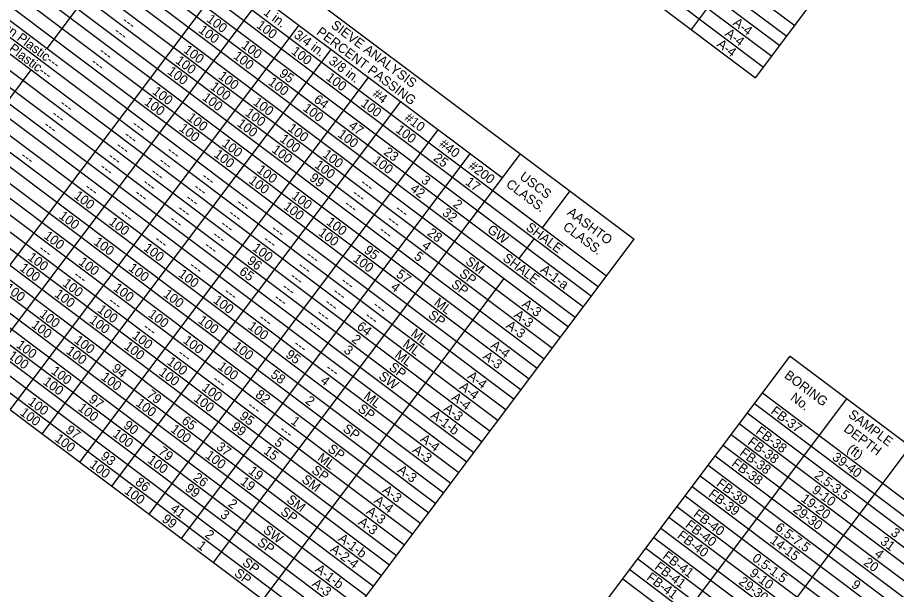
# Model space of a CAD drawing. Extents: x 627484.2 to 627517.5, y 367968.7 to 367996.9.
# Drawn here: x 627506.06 to 627511.18, y 367973.07 to 367976.4 of the extents above; entities that cross this region are included whole.
import ezdxf

# ---------------------------------------------------------------- set-up
doc = ezdxf.new("R2010")
doc.units = 0
doc.layers.add('Default', color=7, linetype='Continuous')
doc.layers.add('R_Survey Control', color=7, linetype='Continuous')

msp = doc.modelspace()

# ---------------------------------------------------------------- linework, layer by layer
at = {"layer": 'Default'}
for p, q in [((627506.113, 367979.7126), (627510.5882, 367976.3521)), ((627506.0661, 367979.6503), (627510.5414, 367976.2898)), ((627506.0251, 367979.5957), (627510.5004, 367976.2352)), ((627505.9783, 367979.5333), (627510.4536, 367976.1728)), ((627505.9315, 367979.4709), (627510.4067, 367976.1104)), ((627505.8846, 367979.4086), (627510.3599, 367976.0481)), ((627505.1779, 367978.4674), (627509.6531, 367975.1069)), ((627510.3599, 367976.0481), (627512.1221, 367978.3948)), ((627505.0169, 367978.253), (627509.4921, 367974.8925)), ((627504.97, 367978.1906), (627509.4453, 367974.8301)), ((627504.9291, 367978.136), (627509.4043, 367974.7755)), ((627504.8822, 367978.0736), (627509.3575, 367974.7131)), ((627504.8354, 367978.0113), (627509.3106, 367974.6508)), ((627504.7944, 367977.9567), (627509.2696, 367974.5962)), ((627504.7476, 367977.8943), (627509.2228, 367974.5338)), ((627504.7007, 367977.8319), (627509.176, 367974.4714)), ((627504.6539, 367977.7696), (627509.1291, 367974.4091)), ((627504.6129, 367977.715), (627509.0882, 367974.3545)), ((627504.5661, 367977.6526), (627509.0413, 367974.2921)), ((627504.5192, 367977.5902), (627508.9945, 367974.2297)), ((627504.4783, 367977.5357), (627508.9535, 367974.1752)), ((627504.4314, 367977.4733), (627508.9067, 367974.1128)), ((627504.3846, 367977.4109), (627508.8598, 367974.0504)), ((627504.3377, 367977.3486), (627508.813, 367973.9881)), ((627504.2909, 367977.2862), (627508.7662, 367973.9257)), ((627504.2441, 367977.2238), (627508.7193, 367973.8633)), ((627504.2031, 367977.1692), (627508.6783, 367973.8087)), ((627504.1563, 367977.1069), (627508.6315, 367973.7464)), ((627506.2325, 367976.2184), (627506.8765, 367977.076)), ((627504.1094, 367977.0445), (627508.5847, 367973.684)), ((627509.9856, 367976.3291), (627510.5301, 367977.0542)), ((627504.0684, 367976.9899), (627508.5437, 367973.6294)), ((627504.0216, 367976.9275), (627508.4968, 367973.567)), ((627503.9806, 367976.873), (627508.4559, 367973.5125)), ((627503.9338, 367976.8106), (627508.409, 367973.4501)), ((627505.6113, 367974.417), (627507.3999, 367976.7988)), ((627503.8869, 367976.7482), (627508.3622, 367973.3877)), ((627503.8401, 367976.6858), (627508.3154, 367973.3253)), ((627507.2945, 367976.6585), (627508.885, 367975.4642)), ((627503.7933, 367976.6235), (627508.2685, 367973.263)), ((627503.7523, 367976.5689), (627508.2275, 367973.2084)), ((627503.7055, 367976.5065), (627508.1807, 367973.146)), ((627505.7985, 367974.2765), (627507.4816, 367976.518)), ((627503.6586, 367976.4441), (627508.1339, 367973.0836)), ((627503.6176, 367976.3896), (627508.0929, 367973.0291)), ((627506.0168, 367974.1125), (627507.6999, 367976.354)), ((627503.5708, 367976.3272), (627508.046, 367972.9667)), ((627503.524, 367976.2648), (627507.9992, 367972.9043)), ((627503.483, 367976.2103), (627507.9582, 367972.8497)), ((627506.2039, 367973.972), (627507.8871, 367976.2135)), ((627503.4361, 367976.1479), (627507.9114, 367972.7874)), ((627503.3893, 367976.0855), (627507.8646, 367972.725)), ((627505.9573, 367975.852), (627506.1388, 367976.0937)), ((627506.4222, 367973.8081), (627508.1054, 367976.0496)), ((627506.6093, 367973.6676), (627508.2925, 367975.9091)), ((627506.8276, 367973.5037), (627508.5108, 367975.7452)), ((627507.0147, 367973.3631), (627508.6979, 367975.6047)), ((627507.2018, 367973.2226), (627508.9904, 367975.6045)), ((627508.8294, 367975.3901), (627509.4921, 367974.8925)), ((627509.1179, 367975.1735), (627509.2789, 367975.3879)), ((627508.9832, 367974.9942), (627509.071, 367975.1111)), ((627507.8646, 367972.725), (627509.6531, 367975.1069)), ((627507.4903, 367973.006), (627508.8954, 367974.8772)), ((627508.7721, 367972.0435), (627510.5607, 367974.4254)), ((627510.5607, 367974.4254), (627515.0359, 367971.0649)), ((627510.3997, 367974.211), (627514.8749, 367970.8505)), ((627509.1034, 367971.7947), (627510.892, 367974.1766)), ((627510.3528, 367974.1486), (627514.8281, 367970.7881)), ((627510.3118, 367974.094), (627514.7871, 367970.7335)), ((627510.265, 367974.0317), (627514.7402, 367970.6712)), ((627510.2182, 367973.9693), (627514.6934, 367970.6088)), ((627509.4738, 367971.5166), (627511.2623, 367973.8985)), ((627510.1713, 367973.9069), (627514.6466, 367970.5464)), ((627510.1245, 367973.8445), (627514.5997, 367970.484)), ((627510.0835, 367973.79), (627514.5588, 367970.4295)), ((627510.0367, 367973.7276), (627514.5119, 367970.3671)), ((627509.9898, 367973.6652), (627514.4651, 367970.3047)), ((627509.9489, 367973.6106), (627514.4241, 367970.2501)), ((627509.902, 367973.5483), (627514.3773, 367970.1878)), ((627509.8552, 367973.4859), (627514.3304, 367970.1254)), ((627509.8083, 367973.4235), (627514.2836, 367970.063)), ((627509.7674, 367973.3689), (627514.2426, 367970.0084)), ((627509.7205, 367973.3066), (627514.1958, 367969.9461)), ((627509.6737, 367973.2442), (627514.1489, 367969.8837)), ((627509.6269, 367973.1818), (627514.1021, 367969.8213)), ((627509.5859, 367973.1273), (627514.0611, 367969.7667))]:
    msp.add_line(p, q, dxfattribs=at)
at = {"layer": 'R_Survey Control'}
msp.add_line((627510.5607, 367974.4254), (627510.5607, 367974.4254), dxfattribs=at)

# ---------------------------------------------------------------- texts
at = {"layer": 'Default'}
for s, p in [('1 in.', (627507.4882, 367976.4207)), ('---Non Plastic---', (627505.8691, 367976.4081)), ('100', (627507.1571, 367976.3798)), ('A-4', (627510.2239, 367976.3596)), ('---Non Plastic---', (627505.8222, 367976.3457)), ('---', (627506.6646, 367976.3716)), ('100', (627507.1103, 367976.3174)), ('100', (627507.4477, 367976.3445)), ('PERCENT PASSING', (627507.797, 367976.3049)), ('SIEVE ANALYSIS', (627507.8818, 367976.3444)), ('---', (627506.6177, 367976.3093)), ('3/4 in.', (627507.6656, 367976.2875)), ('A-4', (627510.1771, 367976.2972)), ('100', (627507.3598, 367976.2275)), ('A-4', (627510.1303, 367976.2349)), ('---', (627506.5299, 367976.1923)), ('100', (627507.0225, 367976.2004)), ('100', (627507.313, 367976.1652)), ('100', (627507.6504, 367976.1923)), ('---', (627506.4831, 367976.1299)), ('100', (627506.9756, 367976.1381)), ('3/8 in.', (627507.8683, 367976.1353)), ('100', (627506.9288, 367976.0757)), ('95', (627507.5798, 367976.0624)), ('100', (627507.2252, 367976.0482)), ('100', (627507.5157, 367976.013)), ('100', (627507.8531, 367976.0401)), ('100', (627506.841, 367975.9587)), ('100', (627507.1783, 367975.9859)), ('100', (627507.1315, 367975.9235)), ('64', (627507.7815, 367975.9109)), ('#4', (627508.1234, 367975.9438)), ('---', (627506.3016, 367975.8883)), ('100', (627506.7941, 367975.8964)), ('100', (627507.4279, 367975.896)), ('100', (627507.7184, 367975.8607)), ('100', (627508.0558, 367975.8878)), ('---', (627506.2548, 367975.8259)), ('100', (627507.0437, 367975.8065)), ('100', (627507.3811, 367975.8336)), ('#10', (627508.3097, 367975.8039)), ('---', (627506.2079, 367975.7635)), ('---', (627506.7227, 367975.7671)), ('100', (627506.9969, 367975.7442)), ('100', (627507.3342, 367975.7713)), ('47', (627507.9845, 367975.7585)), ('100', (627507.6306, 367975.7438)), ('100', (627507.9211, 367975.7085)), ('100', (627508.2585, 367975.7356)), ('---', (627506.6759, 367975.7047)), ('100', (627507.2464, 367975.6543)), ('100', (627507.5838, 367975.6814)), ('#40', (627508.5124, 367975.6517)), ('---', (627506.6291, 367975.6424)), ('---', (627506.9254, 367975.6149)), ('100', (627507.1996, 367975.5919)), ('100', (627507.5369, 367975.619)), ('100', (627507.8333, 367975.5916)), ('23', (627508.1885, 367975.6053)), ('---', (627506.0733, 367975.5842)), ('---', (627506.5822, 367975.58)), ('100', (627508.1238, 367975.5563)), ('25', (627508.4784, 367975.5705)), ('---', (627506.5354, 367975.5176)), ('---', (627506.8786, 367975.5525)), ('100', (627507.4491, 367975.5021)), ('100', (627507.7865, 367975.5292)), ('#200', (627508.6832, 367975.5234)), ('---', (627506.8318, 367975.4901)), ('---', (627507.1282, 367975.4627)), ('100', (627507.4023, 367975.4397)), ('99', (627507.7561, 367975.4545)), ('3', (627508.4074, 367975.4409)), ('USCS', (627508.9806, 367975.4614)), ('---', (627506.4476, 367975.4007)), ('---', (627506.7849, 367975.4278)), ('---', (627508.0524, 367975.427)), ('42', (627508.343, 367975.3917)), ('17', (627508.6649, 367975.4305)), ('CLASS.', (627508.9013, 367975.4178)), ('100', (627506.3843, 367975.3506)), ('---', (627506.7381, 367975.3654)), ('---', (627507.0813, 367975.4003)), ('100', (627507.6518, 367975.3499)), ('---', (627508.0056, 367975.3647)), ('---', (627507.0345, 367975.3379)), ('---', (627507.3309, 367975.3105)), ('100', (627507.605, 367975.2875)), ('---', (627507.9588, 367975.3023)), ('2', (627508.5932, 367975.3014)), ('100', (627506.2965, 367975.2337)), ('---', (627506.6503, 367975.2485)), ('---', (627506.9876, 367975.2756)), ('---', (627507.284, 367975.2481)), ('---', (627508.2551, 367975.2748)), ('32', (627508.5301, 367975.2512)), ('AASHTO', (627509.2576, 367975.2534)), ('100', (627506.587, 367975.1984)), ('---', (627506.9408, 367975.2132)), ('100', (627507.8545, 367975.1977)), ('---', (627508.2083, 367975.2124)), ('---', (627507.2372, 367975.1857)), ('---', (627507.5336, 367975.1582)), ('100', (627507.8077, 367975.1353)), ('---', (627508.1615, 367975.1501)), ('28', (627508.4428, 367975.1339)), ('GW', (627508.792, 367975.1521)), ('SHALE', (627509.017, 367975.1661)), ('CLASS.', (627509.2327, 367975.169)), ('100', (627506.2087, 367975.1167)), ('100', (627506.4992, 367975.0814)), ('---', (627506.853, 367975.0962)), ('---', (627507.1904, 367975.1233)), ('---', (627507.4867, 367975.0959)), ('100', (627506.7898, 367975.0462)), ('---', (627507.1435, 367975.061)), ('100', (627507.4235, 367975.0458)), ('95', (627508.0745, 367975.0325)), ('4', (627508.4115, 367975.0599)), ('100', (627506.115, 367974.992)), ('---', (627506.1783, 367975.042)), ('---', (627507.7363, 367975.006)), ('100', (627508.0104, 367974.9831)), ('5', (627508.3657, 367974.9967)), ('SHALE', (627508.8823, 367974.9868)), ('100', (627506.0682, 367974.9296)), ('100', (627506.4114, 367974.9645)), ('100', (627506.7019, 367974.9292)), ('---', (627507.0557, 367974.944)), ('96', (627507.393, 367974.9712)), ('---', (627507.6895, 367974.9436)), ('SM', (627508.665, 367974.9671)), ('---', (627506.381, 367974.8898)), ('100', (627506.9925, 367974.894)), ('65', (627507.3471, 367974.9081)), ('57', (627508.2609, 367974.8925)), ('SP', (627508.6294, 367974.8962)), ('A-1-a', (627509.1016, 367974.9197)), ('100', (627506.3177, 367974.8398)), ('---', (627507.6426, 367974.8813)), ('---', (627507.939, 367974.8538)), ('SP', (627508.5826, 367974.8338)), ('100', (627505.9804, 367974.8126)), ('100', (627506.2709, 367974.7774)), ('100', (627506.6141, 367974.8123)), ('100', (627506.9046, 367974.777)), ('---', (627507.2584, 367974.7918)), ('---', (627507.5958, 367974.8189)), ('---', (627507.8922, 367974.7914)), ('4', (627508.23, 367974.8182)), ('---', (627506.5837, 367974.7376)), ('100', (627507.1952, 367974.7417)), ('---', (627507.5489, 367974.7565)), ('ML', (627508.4817, 367974.7267)), ('100', (627506.5204, 367974.6875)), ('---', (627507.8453, 367974.7291)), ('---', (627508.1261, 367974.7133)), ('A-3', (627508.9948, 367974.7194)), ('100', (627506.1831, 367974.6604)), ('100', (627506.4736, 367974.6252)), ('100', (627506.8168, 367974.6601)), ('100', (627507.1074, 367974.6248)), ('---', (627507.4611, 367974.6396)), ('---', (627507.7985, 367974.6667)), ('---', (627508.0793, 367974.6509)), ('SP', (627508.4479, 367974.6545)), ('A-3', (627508.9479, 367974.657)), ('100', (627506.1362, 367974.5981)), ('---', (627506.7864, 367974.5854)), ('100', (627507.3979, 367974.5895)), ('---', (627507.7517, 367974.6043)), ('64', (627508.0323, 367974.5887)), ('A-3', (627508.9011, 367974.5947)), ('100', (627506.7232, 367974.5353)), ('2', (627508.0019, 367974.5139)), ('ML', (627508.3471, 367974.5474)), ('100', (627506.0484, 367974.4811)), ('100', (627506.3858, 367974.5082)), ('100', (627506.6763, 367974.4729)), ('100', (627507.0195, 367974.5078)), ('100', (627507.3101, 367974.4726)), ('---', (627507.6638, 367974.4874)), ('ML', (627508.3002, 367974.485)), ('A-4', (627508.8117, 367974.4789)), ('100', (627506.0016, 367974.4187)), ('100', (627506.339, 367974.4458)), ('---', (627506.9891, 367974.4332)), ('95', (627507.6178, 367974.4244)), ('3', (627507.9564, 367974.4506)), ('ML', (627508.2534, 367974.4226)), ('A-3', (627508.7665, 367974.4154)), ('100', (627506.9259, 367974.3831)), ('100', (627506.2511, 367974.3289)), ('94', (627506.6047, 367974.3438)), ('100', (627506.879, 367974.3207)), ('100', (627507.2223, 367974.3556)), ('58', (627507.5297, 367974.3076)), ('---', (627507.851, 367974.3469)), ('SP', (627508.2196, 367974.3505)), ('BORING', (627510.5225, 367974.3036)), ('100', (627506.2043, 367974.2665)), ('100', (627506.5417, 367974.2936)), ('---', (627507.1918, 367974.2809)), ('4', (627507.8202, 367974.2724)), ('SW', (627508.1593, 367974.2982)), ('A-4', (627508.6771, 367974.2996)), ('100', (627507.1286, 367974.2309)), ('A-4', (627508.6302, 367974.2372)), ('97', (627506.4704, 367974.1642)), ('79', (627506.8077, 367974.1914)), ('100', (627507.0817, 367974.1685)), ('82', (627507.4414, 367974.1911)), ('2', (627507.7326, 367974.1553)), ('ML', (627508.0719, 367974.1809)), ('A-4', (627508.5834, 367974.1748)), ('No.', (627510.5581, 367974.1737)), ('100', (627506.1165, 367974.1496)), ('100', (627506.407, 367974.1143)), ('100', (627506.7444, 367974.1414)), ('---', (627507.3945, 367974.1287)), ('SP', (627508.0381, 367974.1088)), ('A-3', (627508.5381, 367974.1113)), ('100', (627506.0696, 367974.0872)), ('95', (627507.3485, 367974.0657)), ('A-1-b', (627508.4627, 367974.0704)), ('FB-37', (627510.4438, 367974.0946)), ('SAMPLE', (627510.8956, 367974.075)), ('90', (627506.6728, 367974.0123)), ('65', (627507.0112, 367974.0386)), ('99', (627507.3009, 367974.0039)), ('1', (627507.6474, 367974.0364)), ('97', (627506.3357, 367973.9849)), ('100', (627506.6097, 367973.9621)), ('100', (627506.9471, 367973.9892)), ('---', (627507.5816, 367973.9882)), ('SP', (627507.9503, 367973.9918)), ('FB-38', (627510.3564, 367973.9774)), ('DEPTH', (627510.8687, 367973.992)), ('100', (627506.2724, 367973.935)), ('5', (627507.5519, 367973.913)), ('A-4', (627508.4019, 367973.9331)), ('FB-38', (627510.3096, 367973.915)), ('79', (627506.8757, 367973.8599)), ('37', (627507.2132, 367973.8869)), ('15', (627507.4888, 367973.8628)), ('SP', (627507.8625, 367973.8749)), ('A-3', (627508.3566, 367973.8696)), ('FB-38', (627510.2627, 367973.8526)), ('(ft)', (627510.8886, 367973.8739)), ('93', (627506.5397, 367973.8318)), ('100', (627506.8124, 367973.8099)), ('100', (627507.1498, 367973.837)), ('ML', (627507.8026, 367973.8223)), ('39-40', (627510.8016, 367973.826)), ('100', (627506.4751, 367973.7828)), ('SP', (627507.7688, 367973.7501)), ('A-3', (627508.2688, 367973.7526)), ('FB-38', (627510.2159, 367973.7903)), ('26', (627507.0783, 367973.7078)), ('19', (627507.4002, 367973.7465)), ('SM', (627507.7107, 367973.6962)), ('2.5-3.5', (627510.6985, 367973.7205)), ('86', (627506.7409, 367973.6807)), ('99', (627507.0316, 367973.6453)), ('19', (627507.3534, 367973.6841)), ('FB-39', (627510.1276, 367973.6737)), ('100', (627506.6778, 367973.6305)), ('A-3', (627508.181, 367973.6357)), ('FB-39', (627510.0808, 367973.6113)), ('9-10', (627510.6832, 367973.6345)), ('2', (627507.2818, 367973.555)), ('SM', (627507.6229, 367973.5793)), ('A-4', (627508.1326, 367973.5745)), ('19-20', (627510.6201, 367973.5843)), ('41', (627506.9464, 367973.5264)), ('3', (627507.2363, 367973.4916)), ('SP', (627507.5873, 367973.5084)), ('A-3', (627508.0873, 367973.5109)), ('FB-40', (627509.9927, 367973.4945)), ('29-30', (627510.5733, 367973.5219)), ('99', (627506.897, 367973.466)), ('A-3', (627508.0405, 367973.4486)), ('FB-40', (627509.9459, 367973.4322)), ('SW', (627507.486, 367973.4016)), ('6.5-7.5', (627510.4702, 367973.4164)), ('3', (627511.1433, 367973.3865)), ('2', (627507.1471, 367973.3756)), ('A-1-b', (627507.9241, 367973.3531)), ('FB-40', (627509.8991, 367973.3698)), ('14-15', (627510.4396, 367973.3419)), ('31', (627511.0815, 367973.3354)), ('1', (627507.1029, 367973.3113)), ('SP', (627507.4527, 367973.3291)), ('A-2-4', (627507.8772, 367973.2908)), ('FB-41', (627509.8141, 367973.2507)), ('0.5-1.5', (627510.3356, 367973.2371)), ('4', (627511.048, 367973.263)), ('SP', (627507.3649, 367973.2122)), ('FB-41', (627509.7672, 367973.1883)), ('20', (627510.985, 367973.2128)), ('SP', (627507.318, 367973.1498)), ('A-1-b', (627507.7894, 367973.1738)), ('FB-41', (627509.7204, 367973.126)), ('9-10', (627510.3202, 367973.1511)), ('A-3', (627507.7712, 367973.0899)), ('29-30', (627510.2571, 367973.1009)), ('9', (627510.9136, 367973.0835))]:
    msp.add_text(s, height=0.055, rotation=323.0968, dxfattribs=at).set_placement(p)

doc.saveas('drawing.dxf')
